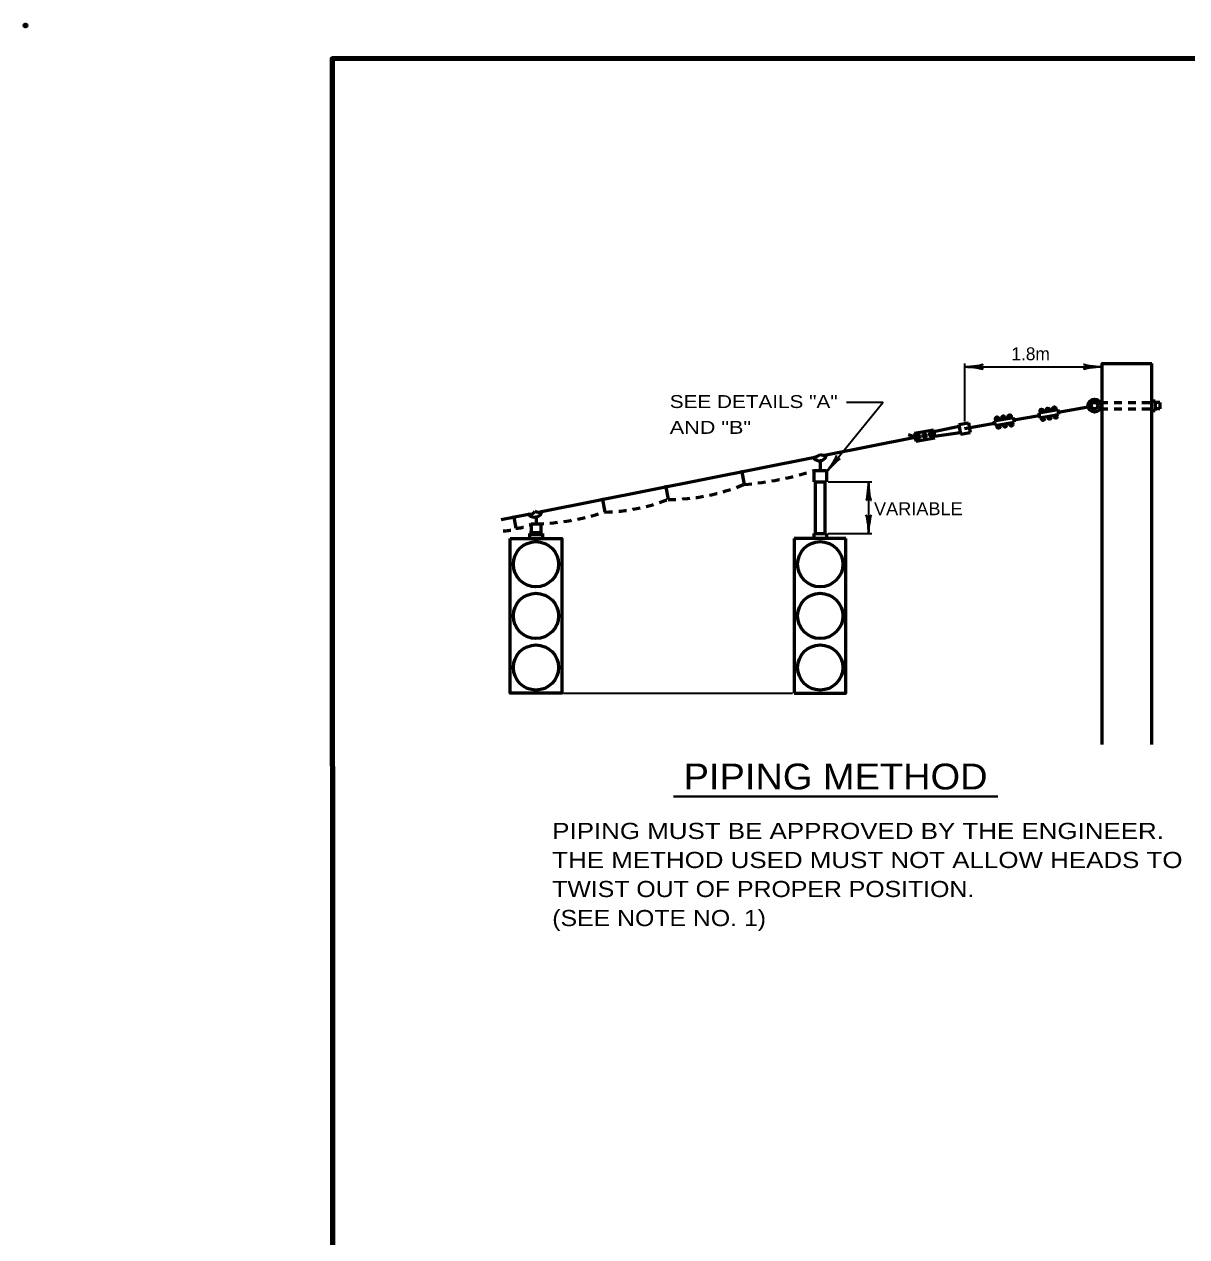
# Model space of a CAD drawing. Extents: x -370 to 486, y -203 to 341.
# Drawn here: x -369.5 to -153.5, y 115.9 to 341.3 of the extents above; entities that cross this region are included whole.
import ezdxf
from ezdxf.enums import TextEntityAlignment as Align

# ---------------------------------------------------------------- set-up
doc = ezdxf.new("R2010")
doc.units = 0
doc.header["$LTSCALE"] = 0.96
doc.header["$PDMODE"] = 32
doc.header["$PDSIZE"] = 0.48
doc.linetypes.add('SHORT_DASHED', pattern=[2.7, 1.5, -1.2])
doc.layers.add('1', color=7, linetype='Continuous', lineweight=53)

msp = doc.modelspace()

# ---------------------------------------------------------------- hatches: boundary and pattern name
at = {"layer": '1'}
for points in [[(-188.4216, 267.9645, 1), (-189.0216, 267.9645, 1)], [(-187.2527, 268.1684, 1), (-187.8527, 268.1684, 1)], [(-186.0748, 268.3723, 1), (-186.6748, 268.3723, 1)], [(-180.1495, 269.424, 1), (-180.7495, 269.424, 1)], [(-178.9806, 269.6279, 1), (-179.5806, 269.6279, 1)], [(-178.6771, 268.1369, 1), (-179.2771, 268.1369, 1)], [(-177.8027, 269.8318, 1), (-178.4027, 269.8318, 1)], [(-177.5037, 268.3454, 1), (-178.1037, 268.3454, 1)], [(-188.1453, 266.4599, 1), (-188.7453, 266.4599, 1)], [(-186.9492, 266.6774, 1), (-187.5492, 266.6774, 1)], [(-185.7758, 266.8859, 1), (-186.3758, 266.8859, 1)], [(-179.8732, 267.9194, 1), (-180.4732, 267.9194, 1)], [(-203.0562, 264.6059, 1), (-203.6562, 264.6059, 1)], [(-201.8747, 264.8156, 1), (-202.4747, 264.8156, 1)], [(-200.6933, 265.0215, 1), (-201.2933, 265.0215, 1)]]:
    msp.add_hatch(color=256, dxfattribs=at).paths.add_polyline_path(points)

# ---------------------------------------------------------------- linework, layer by layer
at = {"layer": '1', "lineweight": 35}
for p, q in [((-194.7282, 267.3995), (-194.7282, 278.1824)), ((-194.7282, 277.5824), (-169.2066, 277.5824)), ((-220.1043, 256.1907), (-212.0043, 256.1907)), ((-212.6043, 256.1907), (-212.6043, 246.5907)), ((-220.1043, 246.5907), (-212.0043, 246.5907)), ((-269.3153, 216.8907), (-226.7153, 216.8907))]:
    msp.add_line(p, q, dxfattribs=at)
at = {"layer": '1'}
for p, q in [((-159.9601, 207.3824), (-159.9601, 278.1824)), ((-159.9601, 271.2824), (-159.3601, 271.2824)), ((-159.3601, 271.2824), (-159.3601, 269.4824)), ((-158.4601, 270.9824), (-159.3601, 270.9824)), ((-158.4601, 270.9824), (-158.4601, 269.7824)), ((-185.633, 267.7316), (-180.9061, 268.5656)), ((-180.9843, 269.0089), (-177.4391, 269.6344)), ((-180.9843, 269.0089), (-180.8279, 268.1224)), ((-180.8279, 268.1224), (-177.2827, 268.7479)), ((-177.4391, 269.6344), (-177.2827, 268.7479)), ((-177.3609, 269.191), (-171.1116, 270.2936)), ((-159.9601, 269.4824), (-159.3601, 269.4824)), ((-158.4601, 269.7824), (-159.3601, 269.7824)), ((-200.4829, 265.5694), (-195.7821, 266.5509)), ((-195.8342, 266.8463), (-194.0615, 267.1589)), ((-195.8342, 266.8463), (-195.5215, 265.0737)), ((-194.7916, 266.1164), (-189.1782, 267.1062)), ((-194.0615, 267.1589), (-193.7489, 265.3862)), ((-189.2564, 267.5494), (-185.7112, 268.1749)), ((-189.2564, 267.5494), (-189.1, 266.6629)), ((-189.1, 266.6629), (-185.5548, 267.2884)), ((-185.7112, 268.1749), (-185.5548, 267.2884)), ((-220.476, 261.2151), (-203.9499, 264.5009)), ((-203.9499, 264.5009), (-205.1528, 264.9603)), ((-204.0802, 265.2395), (-200.535, 265.8648)), ((-204.0802, 265.2395), (-203.8197, 263.7623)), ((-203.8197, 263.7623), (-200.2744, 264.3876)), ((-200.535, 265.8648), (-200.2744, 264.3876)), ((-200.3265, 264.683), (-195.5736, 265.369)), ((-195.5215, 265.0737), (-193.7489, 265.3863)), ((-273.3847, 250.6957), (-222.9309, 260.727)), ((-221.6043, 260.1774), (-221.6043, 258.2907)), ((-236.2065, 258.3935), (-235.7374, 255.734)), ((-222.8043, 258.2907), (-220.4043, 258.2907)), ((-222.8043, 258.2907), (-222.8043, 256.1907)), ((-220.4043, 258.2907), (-220.4043, 256.1907)), ((-250.3333, 255.5848), (-249.8642, 252.9253)), ((-222.8043, 256.1907), (-220.4043, 256.1907)), ((-222.5043, 256.1907), (-222.5043, 246.5907)), ((-220.7043, 256.1907), (-220.7043, 246.5907)), ((-262.1056, 253.2442), (-261.6365, 250.5847)), ((-280.8887, 249.2039), (-275.8307, 250.2094)), ((-278.5869, 249.9673), (-278.17, 247.6037)), ((-275.3153, 248.3907), (-273.5153, 248.3907)), ((-275.3153, 248.3907), (-275.3153, 246.5907)), ((-274.4153, 249.6963), (-274.4153, 248.3907)), ((-273.5153, 248.3907), (-273.5153, 246.5907)), ((-275.6153, 246.5907), (-275.6153, 245.6907)), ((-273.2153, 246.5907), (-273.2153, 245.6907)), ((-222.8043, 246.5907), (-220.4043, 246.5907)), ((-222.8043, 246.5907), (-222.8043, 245.6907)), ((-220.4043, 246.5907), (-220.4043, 245.6907)), ((-226.4043, 245.6907), (-226.4043, 216.8907)), ((-216.8043, 245.6907), (-226.4043, 245.6907))]:
    msp.add_line(p, q, dxfattribs=at)
at = {"layer": '1', "linetype": 'SHORT_DASHED'}
for p, q in [((-169.5601, 270.9824), (-159.9601, 270.9824)), ((-169.5601, 269.7824), (-159.9601, 269.7824))]:
    msp.add_line(p, q, dxfattribs=at)
at = {"layer": '1', "lineweight": 90}
msp.add_line((-275.6153, 246.5907), (-273.2153, 246.5907), dxfattribs=at)
at = {"layer": '1', "lineweight": 40}
msp.add_line((-248.8507, 197.7229), (-188.5942, 197.7229), dxfattribs=at)
at = {"layer": '1', "lineweight": 158}
msp.add_lwpolyline([(479.406, 334.9398), (-312.294, 334.8398), (-312.194, -191.1602)], dxfattribs=at)
at = {"layer": '1'}
for points in [[(-169.2066, 207.3824), (-169.2066, 278.1824), (-159.9601, 278.1824)], [(-223.0643, 260.8456), (-222.5096, 260.3524), (-221.8933, 260.1264), (-221.1948, 260.2497), (-220.6812, 260.599), (-220.5169, 261.0922), (-220.4141, 261.3594)], [(-275.9705, 250.3337), (-275.4158, 249.8405), (-274.7995, 249.6145), (-274.101, 249.7378), (-273.5874, 250.0871), (-273.4231, 250.5803), (-273.3203, 250.8475)], [(-226.4043, 216.8907), (-216.8043, 216.8907), (-216.8043, 245.6907)]]:
    msp.add_lwpolyline(points, dxfattribs=at)
at = {"layer": '1', "lineweight": 35}
msp.add_lwpolyline([(-220.423, 258.0833), (-209.9759, 270.9617), (-216.7296, 270.9617)], dxfattribs=at)
at = {"layer": '1'}
msp.add_lwpolyline([(-279.2153, 245.6907), (-269.6153, 245.6907), (-269.6153, 216.8907), (-279.2153, 216.8907)], close=True, dxfattribs=at)
for centre, radius in [((-170.5993, 270.3824), 1.2), ((-170.6077, 270.3824), 0.6), ((-188.7216, 267.9645), 0.3), ((-187.5527, 268.1684), 0.3), ((-186.3748, 268.3723), 0.3), ((-180.4495, 269.424), 0.3), ((-179.2806, 269.6279), 0.3), ((-178.9771, 268.1369), 0.3), ((-178.1027, 269.8318), 0.3), ((-177.8037, 268.3454), 0.3), ((-188.4453, 266.4599), 0.3), ((-187.2492, 266.6774), 0.3), ((-186.0758, 266.8859), 0.3), ((-180.1732, 267.9194), 0.3), ((-203.3562, 264.6059), 0.3), ((-202.1747, 264.8156), 0.3), ((-200.9933, 265.0215), 0.3), ((-274.4282, 240.8875), 4.2), ((-221.5914, 240.8875), 4.2), ((-274.4282, 231.2874), 4.2), ((-221.5914, 231.2874), 4.2), ((-274.4282, 221.6872), 4.2), ((-221.5914, 221.6872), 4.2)]:
    msp.add_circle(centre, radius, dxfattribs=at)
for centre, radius, start, end in [((-223.2076, 263.2211), 2.5094, 276.33147, 309.71183), ((-220.8995, 263.352), 2.1785, 251.12381, 281.20961), ((-275.5663, 251.2632), 1.0921, 256.47804, 331.55185), ((-273.934, 252.0438), 1.4642, 242.67705, 291.88866)]:
    msp.add_arc(centre, radius, start, end, dxfattribs=at)
at = {"layer": '1', "linetype": 'SHORT_DASHED'}
for centre, radius, start, end in [((-240.2043, 312.3192), 56.7612, 274.51361, 287.85124), ((-249.8016, 289.5374), 36.6123, 269.90064, 292.58925), ((-262.3467, 284.9321), 34.3547, 271.18455, 291.30556), ((-275.7623, 294.5479), 46.1768, 271.67159, 287.81274), ((-278.1881, 253.2402), 5.6365, 270.18364, 300.64191), ((-280.1859, 251.4581), 4.3497, 265.8455, 297.6098)]:
    msp.add_arc(centre, radius, start, end, dxfattribs=at)
at = {"layer": '1', "lineweight": 40}
for centre, major_axis, ratio, start_param, end_param in [((-193.3836, 277.3285), (-2.1077, 0.2108), 0.07063, 3.14071475, 5.41810995), ((-193.3836, 277.3285), (-2.1077, 0.2108), 0.07063, 3.14071475, 5.41810995), ((-193.4188, 277.914), (-2.1428, -0.1874), 0.122415, 0.89635335, 3.14159265), ((-193.4188, 277.914), (-2.1428, -0.1874), 0.122415, 0.89635335, 3.14159265), ((-170.516, 277.2508), (2.1428, 0.1874), 0.122415, 0.89635335, 3.14159265), ((-170.5512, 277.8363), (2.1077, -0.2108), 0.07063, 3.14071475, 5.41810995), ((-219.8556, 259.3091), (-1.2044, -1.7822), 0.122415, 0.89635335, 3.14159265), ((-219.3787, 258.9676), (1.4915, 1.5041), 0.07063, 6.28230741, 8.55970261), ((-212.8582, 254.8461), (0.2108, 2.1077), 0.07063, 3.14071475, 5.41810995), ((-212.8582, 254.8461), (0.2108, 2.1077), 0.07063, 3.14071475, 5.41810995), ((-212.2727, 254.8813), (-0.1874, 2.1428), 0.122415, 0.89635335, 3.14159265), ((-212.2727, 254.8813), (-0.1874, 2.1428), 0.122415, 0.89635335, 3.14159265), ((-212.9359, 247.9001), (0.1874, -2.1428), 0.122415, 0.89635335, 3.14159265), ((-212.3504, 247.9353), (-0.2108, -2.1077), 0.07063, 3.14071475, 5.41810995)]:
    msp.add_ellipse(centre, major_axis=major_axis, ratio=ratio, start_param=start_param, end_param=end_param, dxfattribs=at)
at = {"layer": '1'}
msp.add_point((-369.294, 341.0398), dxfattribs=at)

# ---------------------------------------------------------------- texts
msp.add_text('1.8m', height=2.4, dxfattribs=at).set_placement((-182.4825, 278.8146), align=Align.CENTER)
for s, height, width, p in [('SEE DETAILS "A"', 2.4, 1.2, (-249.5522, 269.9314)), ('AND "B"', 2.4, 1.25, (-249.5522, 265.1314)), ('PIPING MUST BE APPROVED BY THE ENGINEER.', 3, 1.2, (-271.3978, 189.8095)), ('THE METHOD USED MUST NOT ALLOW HEADS TO', 3, 1.2, (-271.3978, 184.4095)), ('TWIST OUT OF PROPER POSITION.', 3, 1.15, (-271.3978, 179.0095)), ('(SEE NOTE NO. 1)', 3, 1.15, (-271.3978, 173.6095))]:
    msp.add_text(s, height=height, dxfattribs=dict(at, width=width)).set_placement(p)
for s, height, width, p in [('VARIABLE', 2.4, 1.05, (-203.3554, 250.0092)), ('PIPING METHOD', 4.8, 1.1, (-218.7351, 199.0197))]:
    msp.add_text(s, height=height, dxfattribs=dict(at, width=width)).set_placement(p, align=Align.CENTER)

doc.saveas('drawing.dxf')
